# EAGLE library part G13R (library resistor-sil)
SIL RESISTOR
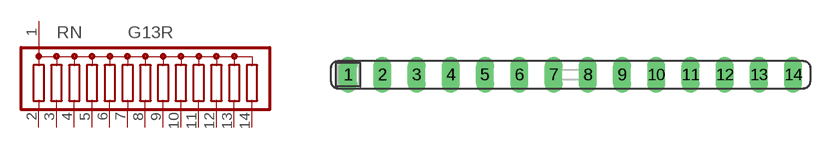
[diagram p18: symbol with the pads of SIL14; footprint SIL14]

Designator prefix RN

## G13R (OC_FARNELL: unknown; OC_NEWARK: unknown)  [SIL14]
1  1  pas
2  2  pas
3  3  pas
4  4  pas
5  5  pas
6  6  pas
7  7  pas
8  8  pas
9  9  pas
10  10  pas
11  11  pas
12  12  pas
13  13  pas
14  14  pas

## Footprint SIL14 (pad centres in mm)
Single In Line
drill 0.813 long: 1 -16.51,0; 2 -13.97,0; 3 -11.43,0; 4 -8.89,0; 5 -6.35,0; 6 -3.81,0; 7 -1.27,0; 8 1.27,0; 9 3.81,0; 10 6.35,0; 11 8.89,0; 12 11.43,0; 13 13.97,0; 14 16.51,0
